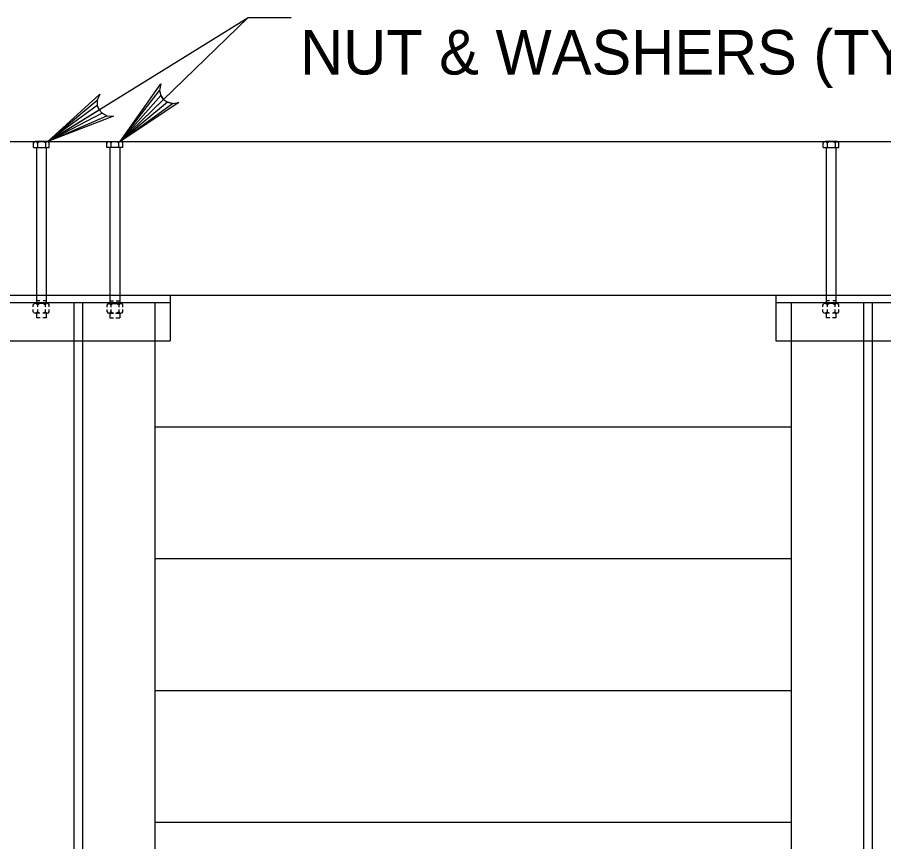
# Model space of a CAD drawing. Extents: x 635440 to 640306, y 296653 to 298484.
# Drawn here: x 639521.1 to 639579.4, y 297985.3 to 298040.7 of the extents above; entities that cross this region are included whole.
import ezdxf

# ---------------------------------------------------------------- set-up
doc = ezdxf.new("R2010")
doc.units = 0
for name, color, linetype in [('3', 7, 'Continuous'), ('4', 7, 'Continuous'), ('52', 7, 'Continuous'), ('8', 7, 'Continuous')]:
    doc.layers.add(name, color=color, linetype=linetype)

msp = doc.modelspace()

# ---------------------------------------------------------------- linework, layer by layer
at = {"layer": '3'}
for p, q in [((639462.829, 298032.371), (639619.557, 298032.371)), ((639522.201, 298031.973), (639522.201, 298032.277)), ((639523.143, 298032.371), (639522.334, 298032.371)), ((639522.38, 298032.366), (639522.38, 298032.366)), ((639522.395, 298032.366), (639522.395, 298032.366)), ((639522.409, 298032.366), (639522.409, 298032.366)), ((639522.418, 298032.352), (639522.418, 298032.352)), ((639522.424, 298032.366), (639522.424, 298032.366)), ((639522.432, 298032.352), (639522.432, 298032.352)), ((639522.438, 298032.366), (639522.438, 298032.366)), ((639522.438, 298032.337), (639522.438, 298032.337)), ((639522.447, 298032.352), (639522.447, 298032.352)), ((639522.453, 298032.366), (639522.453, 298032.366)), ((639522.453, 298032.337), (639522.453, 298032.337)), ((639522.461, 298032.352), (639522.461, 298032.352)), ((639522.461, 298032.323), (639522.461, 298032.323)), ((639522.47, 298032.366), (639522.47, 298032.366)), ((639522.47, 298032.337), (639522.47, 298032.337)), ((639522.47, 298032.308), (639522.47, 298032.308)), ((639522.476, 298032.352), (639522.476, 298032.352)), ((639522.476, 298032.323), (639522.476, 298032.323)), ((639522.476, 298032.294), (639522.476, 298032.294)), ((639522.476, 298032.277), (639522.476, 298031.973)), ((639522.484, 298032.366), (639522.484, 298032.366)), ((639522.484, 298032.337), (639522.484, 298032.337)), ((639522.484, 298032.308), (639522.484, 298032.308)), ((639522.49, 298032.352), (639522.49, 298032.352)), ((639522.49, 298032.323), (639522.49, 298032.323)), ((639522.49, 298032.294), (639522.49, 298032.294)), ((639522.499, 298032.366), (639522.499, 298032.366)), ((639522.499, 298032.337), (639522.499, 298032.337)), ((639522.499, 298032.308), (639522.499, 298032.308)), ((639522.505, 298032.352), (639522.505, 298032.352)), ((639522.505, 298032.323), (639522.505, 298032.323)), ((639522.513, 298032.366), (639522.513, 298032.366)), ((639522.513, 298032.337), (639522.513, 298032.337)), ((639522.513, 298032.308), (639522.513, 298032.308)), ((639522.52, 298032.352), (639522.52, 298032.352)), ((639522.52, 298032.323), (639522.52, 298032.323)), ((639522.528, 298032.366), (639522.528, 298032.366)), ((639522.528, 298032.337), (639522.528, 298032.337)), ((639522.534, 298032.352), (639522.534, 298032.352)), ((639522.534, 298032.323), (639522.534, 298032.323)), ((639522.543, 298032.366), (639522.543, 298032.366)), ((639522.543, 298032.337), (639522.543, 298032.337)), ((639522.549, 298032.352), (639522.549, 298032.352)), ((639522.557, 298032.366), (639522.557, 298032.366)), ((639522.557, 298032.337), (639522.557, 298032.337)), ((639522.565, 298032.352), (639522.565, 298032.352)), ((639522.572, 298032.366), (639522.572, 298032.366)), ((639522.572, 298032.337), (639522.572, 298032.337)), ((639522.578, 298032.352), (639522.578, 298032.352)), ((639522.586, 298032.366), (639522.586, 298032.366)), ((639522.595, 298032.352), (639522.595, 298032.352)), ((639522.601, 298032.366), (639522.601, 298032.366)), ((639522.609, 298032.352), (639522.609, 298032.352)), ((639522.615, 298032.366), (639522.615, 298032.366)), ((639522.63, 298032.366), (639522.63, 298032.366)), ((639522.647, 298032.366), (639522.647, 298032.366)), ((639522.661, 298032.366), (639522.661, 298032.366)), ((639522.676, 298032.366), (639522.676, 298032.366)), ((639522.807, 298032.366), (639522.807, 298032.366)), ((639522.824, 298032.366), (639522.824, 298032.366)), ((639522.838, 298032.366), (639522.838, 298032.366)), ((639522.853, 298032.366), (639522.853, 298032.366)), ((639522.868, 298032.366), (639522.868, 298032.366)), ((639522.874, 298032.352), (639522.874, 298032.352)), ((639522.882, 298032.366), (639522.882, 298032.366)), ((639522.888, 298032.352), (639522.888, 298032.352)), ((639522.897, 298032.366), (639522.897, 298032.366)), ((639522.905, 298032.352), (639522.905, 298032.352)), ((639522.911, 298032.366), (639522.911, 298032.366)), ((639522.911, 298032.337), (639522.911, 298032.337)), ((639522.92, 298032.352), (639522.92, 298032.352)), ((639522.926, 298032.366), (639522.926, 298032.366)), ((639522.926, 298032.337), (639522.926, 298032.337)), ((639522.934, 298032.352), (639522.934, 298032.352)), ((639522.94, 298032.366), (639522.94, 298032.366)), ((639522.94, 298032.337), (639522.94, 298032.337)), ((639522.949, 298032.352), (639522.949, 298032.352)), ((639522.949, 298032.323), (639522.949, 298032.323)), ((639522.957, 298032.366), (639522.957, 298032.366)), ((639522.957, 298032.337), (639522.957, 298032.337)), ((639522.963, 298032.352), (639522.963, 298032.352)), ((639522.963, 298032.323), (639522.963, 298032.323)), ((639522.97, 298032.366), (639522.97, 298032.366)), ((639522.97, 298032.337), (639522.97, 298032.337)), ((639522.97, 298032.308), (639522.97, 298032.308)), ((639522.978, 298032.352), (639522.978, 298032.352)), ((639522.978, 298032.323), (639522.978, 298032.323)), ((639522.986, 298032.366), (639522.986, 298032.366)), ((639522.986, 298032.337), (639522.986, 298032.337)), ((639522.986, 298032.308), (639522.986, 298032.308)), ((639522.993, 298032.352), (639522.993, 298032.352)), ((639522.993, 298032.323), (639522.993, 298032.323)), ((639522.993, 298032.294), (639522.993, 298032.294)), ((639523.001, 298032.366), (639523.001, 298032.366)), ((639523.001, 298032.337), (639523.001, 298032.337)), ((639523.001, 298032.308), (639523.001, 298032.308)), ((639523.007, 298032.352), (639523.007, 298032.352)), ((639523.007, 298032.323), (639523.007, 298032.323)), ((639523.007, 298032.294), (639523.007, 298032.294)), ((639523.009, 298032.352), (639523.009, 298032.352)), ((639523.009, 298032.323), (639523.009, 298032.323)), ((639523.009, 298032.294), (639523.009, 298032.294)), ((639523.009, 298032.277), (639523.009, 298031.973)), ((639523.018, 298032.366), (639523.018, 298032.366)), ((639523.018, 298032.337), (639523.018, 298032.337)), ((639523.018, 298032.308), (639523.018, 298032.308)), ((639523.024, 298032.323), (639523.024, 298032.323)), ((639523.026, 298032.352), (639523.026, 298032.352)), ((639523.032, 298032.366), (639523.032, 298032.366)), ((639523.032, 298032.337), (639523.032, 298032.337)), ((639523.038, 298032.352), (639523.038, 298032.352)), ((639523.047, 298032.366), (639523.047, 298032.366)), ((639523.047, 298032.337), (639523.047, 298032.337)), ((639523.055, 298032.352), (639523.055, 298032.352)), ((639523.061, 298032.366), (639523.061, 298032.366)), ((639523.07, 298032.352), (639523.07, 298032.352)), ((639523.076, 298032.366), (639523.076, 298032.366)), ((639523.09, 298032.366), (639523.09, 298032.366)), ((639523.107, 298032.366), (639523.107, 298032.366)), ((639523.268, 298031.973), (639523.268, 298032.277)), ((639527.147, 298031.973), (639527.147, 298032.277)), ((639527.27, 298032.371), (639528.08, 298032.371)), ((639527.307, 298032.366), (639527.307, 298032.366)), ((639527.322, 298032.366), (639527.322, 298032.366)), ((639527.337, 298032.366), (639527.337, 298032.366)), ((639527.345, 298032.352), (639527.345, 298032.352)), ((639527.351, 298032.366), (639527.351, 298032.366)), ((639527.359, 298032.352), (639527.359, 298032.352)), ((639527.366, 298032.366), (639527.366, 298032.366)), ((639527.366, 298032.337), (639527.366, 298032.337)), ((639527.374, 298032.352), (639527.374, 298032.352)), ((639527.38, 298032.366), (639527.38, 298032.366)), ((639527.38, 298032.337), (639527.38, 298032.337)), ((639527.389, 298032.352), (639527.389, 298032.352)), ((639527.389, 298032.323), (639527.389, 298032.323)), ((639527.397, 298032.366), (639527.397, 298032.366)), ((639527.397, 298032.337), (639527.397, 298032.337)), ((639527.397, 298032.308), (639527.397, 298032.308)), ((639527.403, 298032.352), (639527.403, 298032.352)), ((639527.403, 298032.323), (639527.403, 298032.323)), ((639527.403, 298032.294), (639527.403, 298032.294)), ((639527.403, 298032.277), (639527.403, 298031.973)), ((639527.405, 298032.352), (639527.405, 298032.352)), ((639527.405, 298032.323), (639527.405, 298032.323)), ((639527.405, 298032.294), (639527.405, 298032.294)), ((639527.414, 298032.366), (639527.414, 298032.366)), ((639527.414, 298032.337), (639527.414, 298032.337)), ((639527.414, 298032.308), (639527.414, 298032.308)), ((639527.422, 298032.352), (639527.422, 298032.352)), ((639527.422, 298032.323), (639527.422, 298032.323)), ((639527.422, 298032.294), (639527.422, 298032.294)), ((639527.428, 298032.366), (639527.428, 298032.366)), ((639527.428, 298032.337), (639527.428, 298032.337)), ((639527.428, 298032.308), (639527.428, 298032.308)), ((639527.434, 298032.352), (639527.434, 298032.352)), ((639527.434, 298032.323), (639527.434, 298032.323)), ((639527.443, 298032.366), (639527.443, 298032.366)), ((639527.443, 298032.337), (639527.443, 298032.337)), ((639527.443, 298032.308), (639527.443, 298032.308)), ((639527.449, 298032.352), (639527.449, 298032.352)), ((639527.449, 298032.323), (639527.449, 298032.323)), ((639527.457, 298032.366), (639527.457, 298032.366)), ((639527.457, 298032.337), (639527.457, 298032.337)), ((639527.466, 298032.352), (639527.466, 298032.352)), ((639527.466, 298032.323), (639527.466, 298032.323)), ((639527.472, 298032.366), (639527.472, 298032.366)), ((639527.472, 298032.337), (639527.472, 298032.337)), ((639527.48, 298032.352), (639527.48, 298032.352)), ((639527.487, 298032.366), (639527.487, 298032.366)), ((639527.487, 298032.337), (639527.487, 298032.337)), ((639527.495, 298032.352), (639527.495, 298032.352)), ((639527.501, 298032.366), (639527.501, 298032.366)), ((639527.501, 298032.337), (639527.501, 298032.337)), ((639527.509, 298032.352), (639527.509, 298032.352)), ((639527.516, 298032.366), (639527.516, 298032.366)), ((639527.524, 298032.352), (639527.524, 298032.352)), ((639527.53, 298032.366), (639527.53, 298032.366)), ((639527.539, 298032.352), (639527.539, 298032.352)), ((639527.547, 298032.366), (639527.547, 298032.366)), ((639527.562, 298032.366), (639527.562, 298032.366)), ((639527.576, 298032.366), (639527.576, 298032.366)), ((639527.591, 298032.366), (639527.591, 298032.366)), ((639527.605, 298032.366), (639527.605, 298032.366)), ((639527.739, 298032.366), (639527.739, 298032.366)), ((639527.753, 298032.366), (639527.753, 298032.366)), ((639527.768, 298032.366), (639527.768, 298032.366)), ((639527.782, 298032.366), (639527.782, 298032.366)), ((639527.797, 298032.366), (639527.797, 298032.366)), ((639527.805, 298032.352), (639527.805, 298032.352)), ((639527.812, 298032.366), (639527.812, 298032.366)), ((639527.82, 298032.352), (639527.82, 298032.352)), ((639527.826, 298032.366), (639527.826, 298032.366)), ((639527.834, 298032.352), (639527.834, 298032.352)), ((639527.841, 298032.366), (639527.841, 298032.366)), ((639527.841, 298032.337), (639527.841, 298032.337)), ((639527.849, 298032.352), (639527.849, 298032.352)), ((639527.857, 298032.366), (639527.857, 298032.366)), ((639527.857, 298032.337), (639527.857, 298032.337)), ((639527.864, 298032.352), (639527.864, 298032.352)), ((639527.87, 298032.366), (639527.87, 298032.366)), ((639527.87, 298032.337), (639527.87, 298032.337)), ((639527.878, 298032.352), (639527.878, 298032.352)), ((639527.878, 298032.323), (639527.878, 298032.323)), ((639527.884, 298032.366), (639527.884, 298032.366)), ((639527.884, 298032.337), (639527.884, 298032.337)), ((639527.893, 298032.352), (639527.893, 298032.352)), ((639527.893, 298032.323), (639527.893, 298032.323)), ((639527.901, 298032.366), (639527.901, 298032.366)), ((639527.901, 298032.337), (639527.901, 298032.337)), ((639527.901, 298032.308), (639527.901, 298032.308)), ((639527.907, 298032.352), (639527.907, 298032.352)), ((639527.907, 298032.323), (639527.907, 298032.323)), ((639527.916, 298032.366), (639527.916, 298032.366)), ((639527.916, 298032.337), (639527.916, 298032.337)), ((639527.916, 298032.308), (639527.916, 298032.308)), ((639527.922, 298032.352), (639527.922, 298032.352)), ((639527.922, 298032.323), (639527.922, 298032.323)), ((639527.922, 298032.294), (639527.922, 298032.294)), ((639527.93, 298032.366), (639527.93, 298032.366)), ((639527.93, 298032.337), (639527.93, 298032.337)), ((639527.93, 298032.308), (639527.93, 298032.308)), ((639527.937, 298032.352), (639527.937, 298032.352)), ((639527.937, 298032.323), (639527.937, 298032.323)), ((639527.937, 298032.294), (639527.937, 298032.294)), ((639527.937, 298032.277), (639527.937, 298031.973)), ((639527.945, 298032.366), (639527.945, 298032.366)), ((639527.945, 298032.337), (639527.945, 298032.337)), ((639527.945, 298032.308), (639527.945, 298032.308)), ((639527.951, 298032.323), (639527.951, 298032.323)), ((639527.953, 298032.352), (639527.953, 298032.352)), ((639527.959, 298032.366), (639527.959, 298032.366)), ((639527.959, 298032.337), (639527.959, 298032.337)), ((639527.966, 298032.352), (639527.966, 298032.352)), ((639527.974, 298032.366), (639527.974, 298032.366)), ((639527.974, 298032.337), (639527.974, 298032.337)), ((639527.982, 298032.352), (639527.982, 298032.352)), ((639527.989, 298032.366), (639527.989, 298032.366)), ((639527.997, 298032.352), (639527.997, 298032.352)), ((639528.003, 298032.366), (639528.003, 298032.366)), ((639528.018, 298032.366), (639528.018, 298032.366)), ((639528.034, 298032.366), (639528.034, 298032.366)), ((639528.214, 298031.973), (639528.214, 298032.277)), ((639575.353, 298031.973), (639575.353, 298032.277)), ((639576.295, 298032.371), (639575.487, 298032.371)), ((639575.532, 298032.366), (639575.532, 298032.366)), ((639575.547, 298032.366), (639575.547, 298032.366)), ((639575.562, 298032.366), (639575.562, 298032.366)), ((639575.568, 298032.352), (639575.568, 298032.352)), ((639575.576, 298032.366), (639575.576, 298032.366)), ((639575.585, 298032.352), (639575.585, 298032.352)), ((639575.591, 298032.366), (639575.591, 298032.366)), ((639575.591, 298032.337), (639575.591, 298032.337)), ((639575.599, 298032.352), (639575.599, 298032.352)), ((639575.605, 298032.366), (639575.605, 298032.366)), ((639575.605, 298032.337), (639575.605, 298032.337)), ((639575.614, 298032.352), (639575.614, 298032.352)), ((639575.614, 298032.323), (639575.614, 298032.323)), ((639575.62, 298032.366), (639575.62, 298032.366)), ((639575.62, 298032.337), (639575.62, 298032.337)), ((639575.62, 298032.308), (639575.62, 298032.308)), ((639575.628, 298032.352), (639575.628, 298032.352)), ((639575.628, 298032.323), (639575.628, 298032.323)), ((639575.628, 298032.294), (639575.628, 298032.294)), ((639575.628, 298032.277), (639575.628, 298031.973)), ((639575.637, 298032.366), (639575.637, 298032.366)), ((639575.637, 298032.337), (639575.637, 298032.337)), ((639575.637, 298032.308), (639575.637, 298032.308)), ((639575.643, 298032.352), (639575.643, 298032.352)), ((639575.643, 298032.323), (639575.643, 298032.323)), ((639575.643, 298032.294), (639575.643, 298032.294)), ((639575.649, 298032.366), (639575.649, 298032.366)), ((639575.649, 298032.337), (639575.649, 298032.337)), ((639575.649, 298032.308), (639575.649, 298032.308)), ((639575.657, 298032.352), (639575.657, 298032.352)), ((639575.657, 298032.323), (639575.657, 298032.323)), ((639575.664, 298032.366), (639575.664, 298032.366)), ((639575.664, 298032.337), (639575.664, 298032.337)), ((639575.664, 298032.308), (639575.664, 298032.308)), ((639575.672, 298032.352), (639575.672, 298032.352)), ((639575.672, 298032.323), (639575.672, 298032.323)), ((639575.68, 298032.366), (639575.68, 298032.366)), ((639575.68, 298032.337), (639575.68, 298032.337)), ((639575.687, 298032.352), (639575.687, 298032.352)), ((639575.687, 298032.323), (639575.687, 298032.323)), ((639575.695, 298032.366), (639575.695, 298032.366)), ((639575.695, 298032.337), (639575.695, 298032.337)), ((639575.701, 298032.352), (639575.701, 298032.352)), ((639575.71, 298032.366), (639575.71, 298032.366)), ((639575.71, 298032.337), (639575.71, 298032.337)), ((639575.716, 298032.352), (639575.716, 298032.352)), ((639575.724, 298032.366), (639575.724, 298032.366)), ((639575.724, 298032.337), (639575.724, 298032.337)), ((639575.73, 298032.352), (639575.73, 298032.352)), ((639575.739, 298032.366), (639575.739, 298032.366)), ((639575.745, 298032.352), (639575.745, 298032.352)), ((639575.753, 298032.366), (639575.753, 298032.366)), ((639575.762, 298032.352), (639575.762, 298032.352)), ((639575.768, 298032.366), (639575.768, 298032.366)), ((639575.782, 298032.366), (639575.782, 298032.366)), ((639575.797, 298032.366), (639575.797, 298032.366)), ((639575.814, 298032.366), (639575.814, 298032.366)), ((639575.826, 298032.366), (639575.826, 298032.366)), ((639575.96, 298032.366), (639575.96, 298032.366)), ((639575.974, 298032.366), (639575.974, 298032.366)), ((639575.991, 298032.366), (639575.991, 298032.366)), ((639576.003, 298032.366), (639576.003, 298032.366)), ((639576.02, 298032.366), (639576.02, 298032.366)), ((639576.026, 298032.352), (639576.026, 298032.352)), ((639576.035, 298032.366), (639576.035, 298032.366)), ((639576.041, 298032.352), (639576.041, 298032.352)), ((639576.049, 298032.366), (639576.049, 298032.366)), ((639576.055, 298032.352), (639576.055, 298032.352)), ((639576.064, 298032.366), (639576.064, 298032.366)), ((639576.064, 298032.337), (639576.064, 298032.337)), ((639576.072, 298032.352), (639576.072, 298032.352)), ((639576.078, 298032.366), (639576.078, 298032.366)), ((639576.078, 298032.337), (639576.078, 298032.337)), ((639576.085, 298032.352), (639576.085, 298032.352)), ((639576.093, 298032.366), (639576.093, 298032.366)), ((639576.093, 298032.337), (639576.093, 298032.337)), ((639576.099, 298032.352), (639576.099, 298032.352)), ((639576.099, 298032.323), (639576.099, 298032.323)), ((639576.107, 298032.366), (639576.107, 298032.366)), ((639576.107, 298032.337), (639576.107, 298032.337)), ((639576.116, 298032.352), (639576.116, 298032.352)), ((639576.116, 298032.323), (639576.116, 298032.323)), ((639576.122, 298032.366), (639576.122, 298032.366)), ((639576.122, 298032.337), (639576.122, 298032.337)), ((639576.122, 298032.308), (639576.122, 298032.308)), ((639576.13, 298032.352), (639576.13, 298032.352)), ((639576.13, 298032.323), (639576.13, 298032.323)), ((639576.137, 298032.366), (639576.137, 298032.366)), ((639576.137, 298032.337), (639576.137, 298032.337)), ((639576.137, 298032.308), (639576.137, 298032.308)), ((639576.145, 298032.352), (639576.145, 298032.352)), ((639576.145, 298032.323), (639576.145, 298032.323)), ((639576.145, 298032.294), (639576.145, 298032.294)), ((639576.151, 298032.366), (639576.151, 298032.366)), ((639576.151, 298032.337), (639576.151, 298032.337)), ((639576.151, 298032.308), (639576.151, 298032.308)), ((639576.16, 298032.352), (639576.16, 298032.352)), ((639576.16, 298032.323), (639576.16, 298032.323)), ((639576.16, 298032.294), (639576.16, 298032.294)), ((639576.162, 298032.352), (639576.162, 298032.352)), ((639576.162, 298032.323), (639576.162, 298032.323)), ((639576.162, 298032.294), (639576.162, 298032.294)), ((639576.162, 298032.277), (639576.162, 298031.973)), ((639576.17, 298032.366), (639576.17, 298032.366)), ((639576.17, 298032.337), (639576.17, 298032.337)), ((639576.17, 298032.308), (639576.17, 298032.308)), ((639576.176, 298032.352), (639576.176, 298032.352)), ((639576.176, 298032.323), (639576.176, 298032.323)), ((639576.185, 298032.366), (639576.185, 298032.366)), ((639576.185, 298032.337), (639576.185, 298032.337)), ((639576.191, 298032.352), (639576.191, 298032.352)), ((639576.199, 298032.366), (639576.199, 298032.366)), ((639576.199, 298032.337), (639576.199, 298032.337)), ((639576.205, 298032.352), (639576.205, 298032.352)), ((639576.214, 298032.366), (639576.214, 298032.366)), ((639576.222, 298032.352), (639576.222, 298032.352)), ((639576.228, 298032.366), (639576.228, 298032.366)), ((639576.243, 298032.366), (639576.243, 298032.366)), ((639576.258, 298032.366), (639576.258, 298032.366)), ((639576.418, 298031.973), (639576.418, 298032.277)), ((639522.201, 298031.973), (639523.268, 298031.973)), ((639522.405, 298031.973), (639522.405, 298021.476)), ((639523.061, 298031.973), (639523.061, 298021.476)), ((639528.214, 298031.973), (639527.147, 298031.973)), ((639527.351, 298031.973), (639527.351, 298021.476)), ((639528.007, 298031.973), (639528.007, 298021.476)), ((639575.353, 298031.973), (639576.418, 298031.973)), ((639575.557, 298031.973), (639575.557, 298021.476)), ((639576.214, 298031.973), (639576.214, 298021.476)), ((639462.829, 298022.035), (639619.557, 298022.035)), ((639522.628, 298021.658), (639522.405, 298021.658)), ((639523.061, 298021.658), (639522.854, 298021.658)), ((639527.351, 298021.658), (639527.589, 298021.658)), ((639527.769, 298021.658), (639528.007, 298021.658)), ((639531.397, 298022.035), (639531.397, 298018.96)), ((639572.17, 298022.035), (639572.17, 298018.96)), ((639575.78, 298021.658), (639575.557, 298021.658)), ((639576.214, 298021.658), (639576.006, 298021.658)), ((639522.19, 298021.249), (639522.19, 298021.383)), ((639522.19, 298020.924), (639522.19, 298021.08)), ((639523.134, 298021.476), (639522.324, 298021.476)), ((639522.468, 298021.383), (639522.468, 298021.249)), ((639522.468, 298021.081), (639522.468, 298020.924)), ((639523.001, 298021.383), (639523.001, 298021.249)), ((639523.001, 298021.081), (639523.001, 298020.924)), ((639523.257, 298021.249), (639523.257, 298021.383)), ((639523.257, 298020.924), (639523.257, 298021.081)), ((639527.155, 298021.235), (639527.155, 298021.383)), ((639527.155, 298020.924), (639527.155, 298021.083)), ((639527.28, 298021.476), (639528.089, 298021.476)), ((639527.414, 298021.383), (639527.414, 298021.235)), ((639527.414, 298021.083), (639527.414, 298020.924)), ((639527.947, 298021.383), (639527.947, 298021.235)), ((639527.947, 298021.083), (639527.947, 298020.924)), ((639528.222, 298021.235), (639528.222, 298021.383)), ((639528.222, 298020.924), (639528.222, 298021.083)), ((639575.343, 298021.249), (639575.343, 298021.383)), ((639575.343, 298020.924), (639575.343, 298021.08)), ((639576.287, 298021.476), (639575.476, 298021.476)), ((639575.62, 298021.383), (639575.62, 298021.249)), ((639575.62, 298021.081), (639575.62, 298020.924)), ((639576.153, 298021.383), (639576.153, 298021.249)), ((639576.153, 298021.081), (639576.153, 298020.924)), ((639576.41, 298021.249), (639576.41, 298021.383)), ((639576.41, 298020.924), (639576.41, 298021.081)), ((639522.601, 298020.831), (639522.324, 298020.831)), ((639522.405, 298020.831), (639522.405, 298020.51)), ((639522.643, 298020.51), (639522.405, 298020.51)), ((639523.061, 298020.51), (639522.823, 298020.51)), ((639523.134, 298020.831), (639522.864, 298020.831)), ((639523.061, 298020.831), (639523.061, 298020.51)), ((639527.28, 298020.831), (639527.589, 298020.831)), ((639527.351, 298020.831), (639527.351, 298020.51)), ((639527.351, 298020.51), (639527.589, 298020.51)), ((639527.739, 298020.831), (639528.089, 298020.831)), ((639527.739, 298020.51), (639528.007, 298020.51)), ((639528.007, 298020.831), (639528.007, 298020.51)), ((639575.753, 298020.831), (639575.476, 298020.831)), ((639575.557, 298020.831), (639575.557, 298020.51)), ((639575.795, 298020.51), (639575.557, 298020.51)), ((639576.214, 298020.51), (639575.975, 298020.51)), ((639576.287, 298020.831), (639576.017, 298020.831)), ((639576.214, 298020.831), (639576.214, 298020.51)), ((639519.017, 298018.96), (639531.397, 298018.96)), ((639530.372, 298018.96), (639530.372, 297975.214)), ((639572.17, 298018.96), (639584.55, 298018.96)), ((639573.193, 298018.96), (639573.193, 297975.214)), ((639530.372, 298013.176), (639573.193, 298013.176)), ((639530.372, 298004.317), (639573.193, 298004.317)), ((639530.372, 297995.459), (639573.193, 297995.459)), ((639530.372, 297986.6), (639573.193, 297986.6))]:
    msp.add_line(p, q, dxfattribs=at)
for centre, radius, start, end in [((639522.337, 298032.223), 0.148, 88.17294, 158.71305), ((639522.337, 298032.223), 0.148, 21.28694, 88.17294), ((639522.741, 298031.947), 0.424, 51.05, 128.95), ((639523.136, 298032.236), 0.135, 17.45181, 162.54819), ((639527.273, 298032.236), 0.135, 17.45181, 162.54819), ((639527.669, 298031.947), 0.424, 51.05, 128.95), ((639528.073, 298032.223), 0.148, 91.82706, 158.71306), ((639528.073, 298032.223), 0.148, 21.28694, 91.82706), ((639575.49, 298032.223), 0.148, 88.17294, 158.71305), ((639575.49, 298032.223), 0.148, 21.28694, 88.17294), ((639575.894, 298031.947), 0.424, 51.05, 128.95), ((639576.29, 298032.236), 0.135, 17.45181, 162.54819), ((639522.33, 298021.328), 0.148, 88.17294, 158.71305), ((639522.33, 298021.328), 0.148, 21.28694, 88.17294), ((639522.734, 298021.052), 0.424, 51.05, 128.95), ((639523.129, 298021.341), 0.135, 17.45181, 162.54819), ((639527.285, 298021.341), 0.135, 17.45181, 162.54819), ((639527.68, 298021.052), 0.424, 51.05, 128.95), ((639528.085, 298021.328), 0.148, 91.82706, 158.71306), ((639528.085, 298021.328), 0.148, 21.28694, 91.82706), ((639575.482, 298021.328), 0.148, 88.17294, 158.71305), ((639575.482, 298021.328), 0.148, 21.28694, 88.17294), ((639575.887, 298021.052), 0.424, 51.05, 128.95), ((639576.282, 298021.341), 0.135, 17.45181, 162.54819), ((639522.33, 298020.978), 0.148, 201.28694, 271.82706), ((639522.33, 298020.978), 0.148, 271.82706, 338.71306), ((639522.734, 298021.254), 0.424, 231.05, 256.0077), ((639522.734, 298021.254), 0.424, 284.34274, 308.95), ((639523.129, 298020.965), 0.135, 197.45181, 342.54819), ((639527.285, 298020.965), 0.135, 197.45181, 342.54819), ((639527.68, 298021.254), 0.424, 231.05, 257.49177), ((639527.68, 298021.254), 0.424, 277.88621, 308.95), ((639528.085, 298020.978), 0.148, 201.28694, 268.17294), ((639528.085, 298020.978), 0.148, 268.17294, 338.71305), ((639575.482, 298020.978), 0.148, 201.28694, 271.82706), ((639575.482, 298020.978), 0.148, 271.82706, 338.71306), ((639575.887, 298021.254), 0.424, 231.05, 256.0077), ((639575.887, 298021.254), 0.424, 284.34274, 308.95), ((639576.282, 298020.965), 0.135, 197.45181, 342.54819)]:
    msp.add_arc(centre, radius, start, end, dxfattribs=at)
at = {"layer": '4'}
for points in [[(639523.165, 298032.369), (639536.645, 298040.727)], [(639528.045, 298032.371), (639536.645, 298040.727), (639539.547, 298040.727)]]:
    msp.add_lwpolyline(points, dxfattribs=at)
at = {"layer": '52'}
for points in [[(639528.045, 298032.371), (639530.778, 298036.246), (639530.695, 298035.817), (639530.78, 298035.462), (639530.96, 298035.202), (639531.216, 298035.014), (639531.566, 298034.921), (639531.997, 298034.992), (639528.045, 298032.371), (639531.566, 298034.921), (639531.216, 298035.014), (639528.045, 298032.371), (639530.96, 298035.202), (639530.78, 298035.462), (639528.045, 298032.371), (639530.695, 298035.817)], [(639523.165, 298032.369), (639526.666, 298035.567), (639526.493, 298035.167), (639526.499, 298034.804), (639526.618, 298034.51), (639526.828, 298034.273), (639527.151, 298034.104), (639527.587, 298034.081), (639523.165, 298032.369), (639527.151, 298034.104), (639526.828, 298034.273), (639523.165, 298032.369), (639526.618, 298034.51), (639526.499, 298034.804), (639523.165, 298032.369), (639526.493, 298035.167)]]:
    msp.add_lwpolyline(points, dxfattribs=at)
at = {"layer": '8'}
for p, q in [((639519.017, 298021.543), (639531.397, 298021.543)), ((639524.913, 298021.543), (639524.913, 297930.676)), ((639525.505, 298021.543), (639525.505, 297930.306)), ((639530.372, 298021.543), (639530.372, 298018.96)), ((639572.17, 298021.543), (639584.55, 298021.543)), ((639573.195, 298021.543), (639573.195, 298018.96)), ((639578.066, 298021.543), (639578.066, 297930.676)), ((639578.656, 298021.543), (639578.656, 297930.306))]:
    msp.add_line(p, q, dxfattribs=at)

# ---------------------------------------------------------------- texts
at = {"layer": '4'}
msp.add_text('NUT & WASHERS (TYP.)', height=3.00014, dxfattribs=at).set_placement((639540.152, 298036.881))

doc.saveas('drawing.dxf')
